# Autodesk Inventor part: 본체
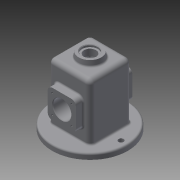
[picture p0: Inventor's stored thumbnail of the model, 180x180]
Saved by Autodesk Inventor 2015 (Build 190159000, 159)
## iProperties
Created: 2021-08
Part Number: 본체
Material: 일반
Document SubType Name: Modeling
Designer: 10462
Density: 1 g/cm^3
Appearance: 기본값
Author: 10462
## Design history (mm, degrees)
sketch "스케치1"
  geometry: C1 r 67 at (0, 0); 1 further point
  constraints: 1 centre point, 1 coincident
  dimensions: "d0" = 134 diameter of C1
extrude "돌출1" new body sketch "스케치1" distance "d1" = 10; taper "d2" = 0 deg
sketch "스케치2"
  geometry: L1 (-37, 37)-(37, 37); L2 (37, 37)-(37, -37); L3 (37, -37)-(-37, -37); L4 (-37, -37)-(-37, 37); L5 (-37, 37)-(37, -37); L6 (37, 37)-(-37, -37); C1 r 67 at (0, 0) reference
  constraints: 12 end point, 2 midpoint, 2 parallel, 1 horizontal, 1 perpendicular
  dimensions: "d3" = 74 distance of L2.end L3.end; "d4" = 74 distance of L1.end L2.end
extrude "돌출2" join sketch "스케치2" distance "d5" = 100; taper "d6" = 0 deg
sketch "스케치4"
  geometry: L1 (12, 70)-(62, 70); L2 (62, 70)-(62, 20); L3 (62, 20)-(12, 20); L4 (12, 20)-(12, 70); L5 (12, 70)-(62, 20); L6 (62, 70)-(12, 20); L7 (-30, -10)-(104, -10) reference; 3 further points
  constraints: 12 end point, 3 midpoint, 2 parallel, 1 horizontal, 1 perpendicular, 1 vertical alignment
  dimensions: "d7" = 50 distance of L1.end L2.end; "d8" = 50 distance of L2.end L3.end; "d11" = 55 distance from line of L7 point (37, 45)
extrude "돌출3" join sketch "스케치4" distance "d9" = 13; taper "d10" = 0 deg
sketch "스케치5"
  geometry: L1 (62, -70)-(12, -70); L2 (12, -70)-(12, -20); L3 (12, -20)-(62, -20); L4 (62, -20)-(62, -70); L5 (62, -70)-(12, -20); L6 (12, -70)-(62, -20); L7 (104, 10)-(-30, 10) reference; 3 further points
  constraints: 12 end point, 3 midpoint, 2 parallel, 1 horizontal, 1 perpendicular, 1 vertical alignment
  dimensions: "d12" = 50 distance of L1.end L2.end; "d13" = 50 distance of L2.end L3.end; "d14" = 55 distance from line of L7 point (37, -45)
extrude "돌출4" join sketch "스케치5" distance "d15" = 13; taper "d16" = 0 deg
fillet "모깎기1" dims "d17" = 8
sketch "스케치6"
  geometry: L1 (-32, -32)-(32, -32); L2 (32, -32)-(32, 32); L3 (32, 32)-(-32, 32); L4 (-32, 32)-(-32, -32); L5 (-32, -32)-(32, 32); L6 (32, -32)-(-32, 32); C1 r 67 at (0, 0) reference
  constraints: 12 end point, 2 midpoint, 2 parallel, 1 horizontal, 1 perpendicular
  dimensions: "d18" = 64 distance of L1.start L1.end; "d19" = 64 distance of L1.end L2.end
extrude "돌출5" cut sketch "스케치6" distance "d20" = 105; taper "d21" = 0 deg
sketch "스케치8"
  geometry: L1 (32, 0)-(32, 27.5); L2 (32, 0)-(32, 105) reference; L3 (32, 27.5)-(25, 27.5); L4 (25, 27.5)-(25, 77.5); L5 (25, 77.5)-(32, 77.5); L6 (-32, 0)-(-32, 27.5); L7 (-32, 0)-(-32, 105) reference; L8 (-32, 27.5)-(-25, 27.5); L9 (-25, 27.5)-(-25, 77.5); L10 (-25, 77.5)-(-32, 77.5); 1 further point
  constraints: 16 end point, 4 perpendicular, 4 point on line, 2 horizontal
  dimensions: "d22" = 27.5 distance of L1.start L1.end; "d23" = 7 distance of L1.end L3.end; "d24" = 50 distance of L3.end L4.end; "d25" = 27.5 distance of L6.start L6.end; "d26" = 7 distance of L6.end L8.end; "d27" = 50 distance of L8.end L9.end
extrude "돌출6" join sketch "스케치8" stored distance "d28" = 64; taper "d29" = 0 deg
sketch "스케치9"
  geometry: L1 (62, 28)-(62, 62) reference; C1 r 16 at (37, 45); 2 further points
  constraints: 1 centre point, 1 horizontal alignment, 1 midpoint, 1 vertical alignment
  dimensions: "d34" = 32 diameter of C1
hole "구멍1" sketch "스케치9" at (37, 45) diameter "d35" = 32; stored, may be unused: countersink angle "d39" = 90 deg, drill point angle "d41" = 118 deg; dims "d36" = 6, "d37" = 4, "d38" = 2, "d40" = 8
chamfer "모따기1" distance "d42" = 1; stored, may be unused: second distance "d43" = 2, angle "d44" = 45 deg
sketch "스케치10"
  geometry: C1 r 20 at (0, 0); 1 further point
  constraints: 1 centre point, 1 coincident
  dimensions: "d45" = 40 diameter of C1
extrude "돌출7" join sketch "스케치10" distance "d46" = 10; taper "d47" = 0 deg
sketch "스케치11"
  geometry: C1 r 20 at (0, 0) reference
hole "구멍2" sketch "스케치11" at (0, 0) diameter "d48" = 21; stored, may be unused: countersink angle "d52" = 90 deg, drill point angle "d54" = 118 deg; dims "d49" = 6, "d50" = 28, "d51" = 4, "d53" = 8
chamfer "모따기2" distance "d55" = 1; stored, may be unused: second distance "d56" = 2, angle "d57" = 45 deg
fillet "모깎기2" dims "d58" = 8
sketch "스케치12"
  geometry: L1 (17, -110)-(57, -110) reference; 2 further points
  constraints: 1 vertical alignment, 1 other
  dimensions: "d59" = 28 distance from line of point (37, -82) L1
feature "엠보싱1" sketch "스케치12" dims "d7" = 50, "d8" = 50, "d11" = 55, "d60" = 0.5, "d61" = 0
sketch "스케치13"
  geometry: C1 r 67 at (0, 0) reference; 2 further points
  constraints: 2 horizontal alignment
  dimensions: "d62" = 55 distance of C1.centre point (-55, 0); "d63" = 55 distance of C1.centre point (55, 0)
hole "구멍3" sketch "스케치13" at (-55, 0), (55, 0) diameter "d64" = 9; stored, may be unused: countersink angle "d68" = 90 deg, drill point angle "d70" = 118 deg; dims "d65" = 6, "d66" = 28, "d67" = 4, "d69" = 8
sketch "스케치14"
  geometry: A1 r 8 centre (20, 28) between (12, 28) and (20, 20) reference; A2 r 8 centre (54, 28) between (54, 20) and (62, 28) reference; A3 r 8 centre (54, 62) between (62, 62) and (54, 70) reference; A4 r 8 centre (20, 62) between (20, 70) and (12, 62) reference; 1 further point
hole "구멍4" sketch "스케치14" at (54, 28), (54, 62), (20, 62), (20, 28) diameter "d71" = 3.242; stored, may be unused: countersink angle "d75" = 90 deg, drill point angle "d77" = 118 deg; dims "d72" = 8, "d73" = 28, "d74" = 4, "d76" = 10
sketch "스케치15"
  geometry: A1 r 8 centre (54, -62) between (54, -70) and (62, -62) reference; A2 r 8 centre (54, -28) between (62, -28) and (54, -20) reference; A3 r 8 centre (20, -28) between (20, -20) and (12, -28) reference; A4 r 8 centre (20, -62) between (12, -62) and (20, -70) reference; 1 further point
hole "구멍5" sketch "스케치15" at (54, -62), (20, -62), (20, -28), (54, -28) diameter "d78" = 3.242; stored, may be unused: countersink angle "d82" = 90 deg, drill point angle "d84" = 118 deg; dims "d79" = 8, "d80" = 28, "d81" = 4, "d83" = 10
fillet "모깎기3" dims "d85" = 3
fillet "모깎기4" dims "d86" = 3
fillet "모깎기5" dims "d87" = 8
fillet "모깎기6" dims "d88" = 3
fillet "모깎기7" dims "d89" = 3
fillet "모깎기8" dims "d90" = 3
feature "면 기울기5" dims angle "d92" = 20 deg
feature "면 기울기6" dims angle "d93" = 20 deg
feature "면 기울기7" dims angle "d94" = 20 deg
feature "면 기울기8" dims angle "d95" = 20 deg
feature "면 기울기9" dims angle "d96" = 6 deg
fillet "모깎기10" dims "d97" = 3
node "솔리드1"
